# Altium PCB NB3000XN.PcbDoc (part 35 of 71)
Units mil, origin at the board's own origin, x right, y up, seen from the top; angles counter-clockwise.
Board outline 9527.56 x 6929.77 mil, 6 copper layers (Top Layer, GND+SHIELD, MidLayer1, MidLayer2, P2 - 3V3+5V0, Bottom Layer), stack 62.375 mil thick; 832 components, 1027 nets, 4655 pads, 4981 vias.
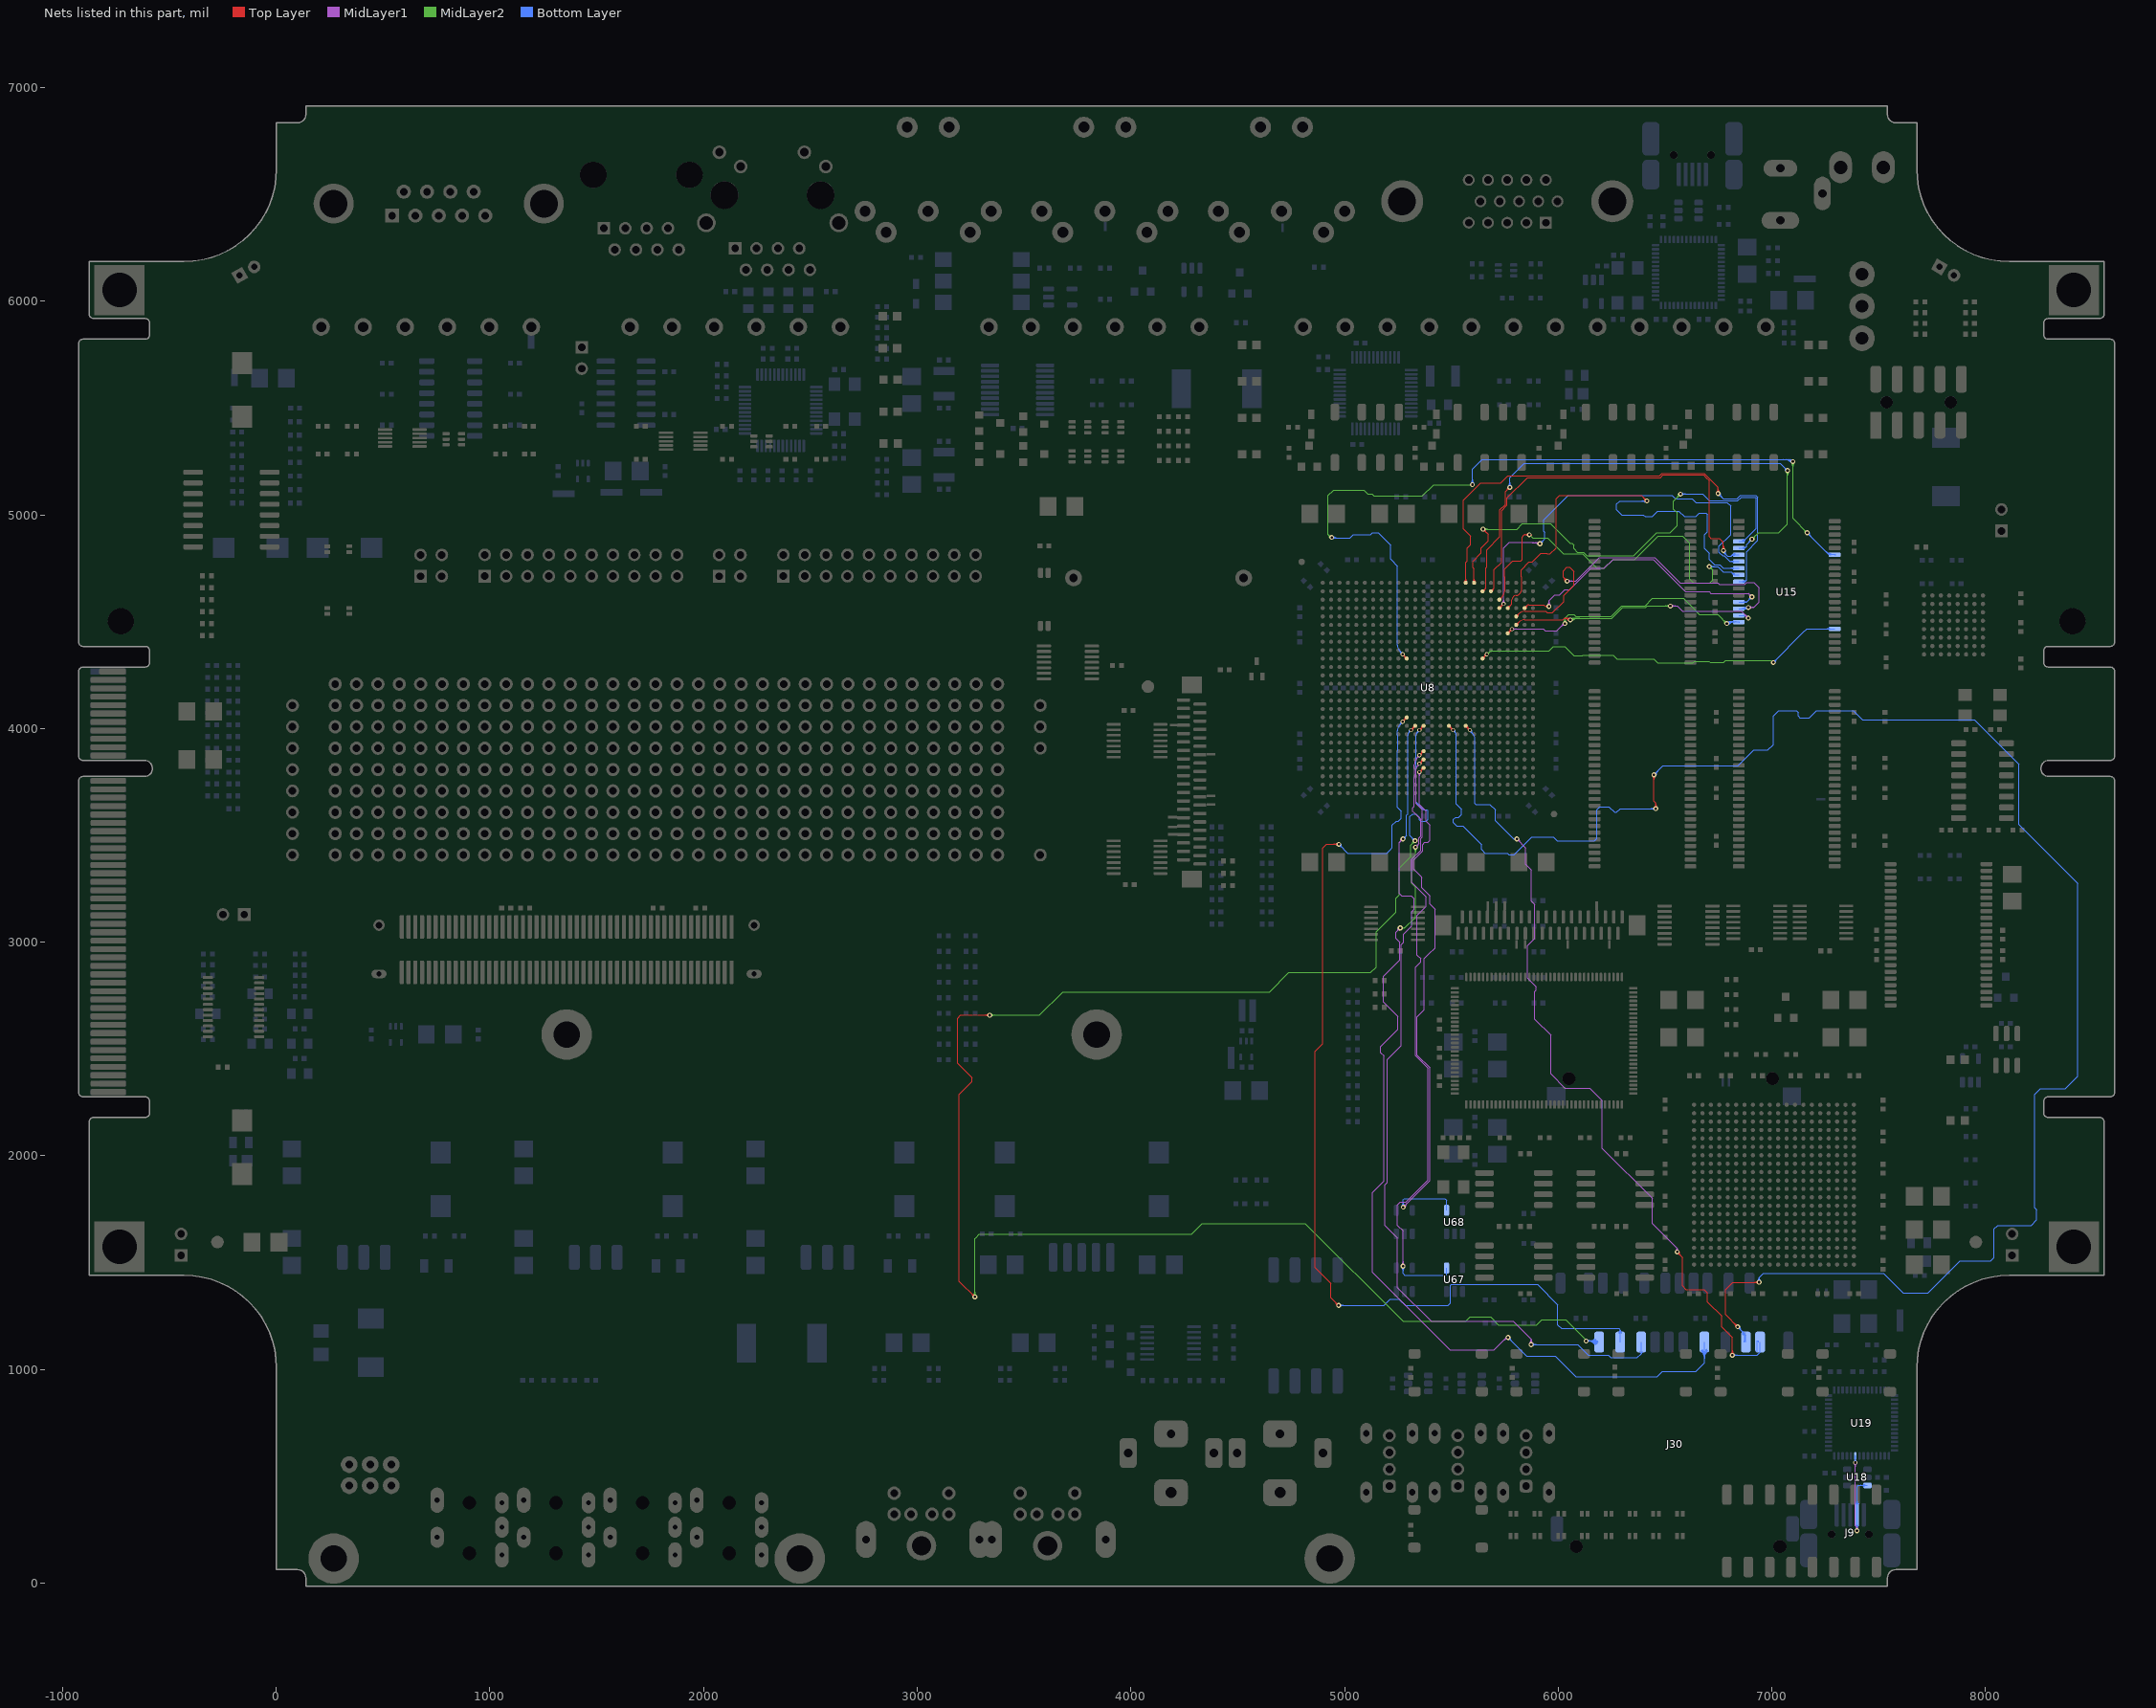
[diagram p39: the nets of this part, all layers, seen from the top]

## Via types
v1: diameter 23, hole 11.81, Top Layer to Bottom Layer, 3672 vias
v2: diameter 26, hole 11.81, Top Layer to Bottom Layer, 461 vias
v3: diameter 19, hole 11.81, Top Layer to Bottom Layer, tented both sides, 396 vias
v4: diameter 23.62, hole 11.81, Top Layer to Bottom Layer, 288 vias
v5: diameter 20, hole 11.81, Top Layer to Bottom Layer, 91 vias
v6: diameter 23, hole 11.81, Top Layer to Bottom Layer, tented both sides, 50 vias
v7: diameter 31, hole 11.81, Top Layer to Bottom Layer, 15 vias
v8: diameter 27.56, hole 11.81, Top Layer to Bottom Layer, tented both sides, 4 vias
v9: diameter 29, hole 11.81, Top Layer to Bottom Layer, 3 vias
v10: diameter 21, hole 11.81, Top Layer to Bottom Layer, 1 vias

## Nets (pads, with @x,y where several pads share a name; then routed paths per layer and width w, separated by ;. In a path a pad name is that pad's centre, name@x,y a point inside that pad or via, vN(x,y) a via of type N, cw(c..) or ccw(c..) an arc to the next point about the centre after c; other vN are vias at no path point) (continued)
DB_SRAM2.D8: U8.G23 U15.29 | length 1778.3
  Top Layer w4: U8.G23@5764.02,4445.91 v3(5783.7,4465.59) ; U8.G23@5764.02,4453.25 ccw(c5764.02,4470.97) 5776.55,4458.44 ccw(c5789.08,4445.91) U8.G23@5771.36,4445.91 ; U8.G23@5764.02,4453.41 ccw(c5764.02,4471.51) 5776.82,4458.71 ccw(c5789.62,4445.91) U8.G23@5771.52,4445.91 ; 5770.9,4452.79 cw(c5783.7,4439.98) 5783.7,4458.09 ccw(c5783.7,4439.98) 5770.9,4452.79 ; 5770.9,4452.79 ccw(c5758.09,4465.59) 5776.2,4465.59 cw(c5758.09,4465.59) 5770.9,4452.79
  MidLayer1 w4: v3(5783.7,4465.59) 5861.38,4465.59 5910,4465.59 5920,4465.59 5924.74,4465.59 5928.74,4465.59 5931.86,4465.59 5931.86,4465.37 5938.86,4458.37 5992.86,4458.37 6026.19,4491.71 v1(6031.86,4491.71) ; v3@5788.89,4460.4 cw(c5801.43,4447.86) 5801.43,4465.59 cw(c5801.43,4483.32) v3@5788.89,4470.78 ; 6005.97,4471.48 cw(c6031.86,4445.59) v1@6031.86,4482.21 ; 6012.79,4478.31 cw(c6031.86,4459.25) v1@6031.86,4486.21 ; 6019.62,4485.14 cw(c6031.86,4472.91) v1@6031.86,4490.21 ; 6019.65,4485.16 ccw(c6013.1,4491.71) v1@6022.36,4491.71 ; 5801.81,4465.59 cw(c5801.81,4483.7) 5789,4470.89 ccw(c5801.81,4483.7) 5801.81,4465.59 ; 5801.81,4465.59 ccw(c5801.81,4447.48) 5789,4460.29 cw(c5801.81,4447.48) 5801.81,4465.59
  MidLayer2 w4: v1@6025.14,4498.43 ccw(c6008.92,4514.64) 6031.86,4514.64 ccw(c6054.79,4514.64) v1@6038.57,4498.43 ; v1@6027.97,4495.6 ccw(c6018.58,4504.99) 6031.86,4504.99 ccw(c6045.14,4504.99) v1@6035.75,4495.6 ; v1(6031.86,4491.71) 6031.86,4516.71 6048.52,4533.37 6073.52,4533.37 6081.86,4525.04 6248.52,4525.04 6298.52,4575.04 6406.86,4575.04 6441.52,4609.71 6585.88,4609.71 6640.29,4555.29 ; 6640,4555 6661.29,4533.71 6747.19,4533.71 v1(6789.19,4491.71) ; v1@6779.69,4491.71 ccw(c6756.76,4491.71) 6772.97,4507.93 ccw(c6789.19,4524.14) v1@6789.19,4501.21 ; v1@6783.69,4491.71 ccw(c6770.41,4491.71) 6779.8,4501.1 ccw(c6789.19,4510.49) v1@6789.19,4497.21
  Bottom Layer w4: v1@6787.42,4493.48 cw(c6803.27,4477.63) 6803.27,4500.04 ; v1(6789.19,4491.71) 6797.52,4500.04 6845.59,4500.04 6848.52,4500.04 6848.52,4498.27 U15.29@6845.59,4498.27 ; v1@6790.25,4490.65 cw(c6812.93,4467.97) 6812.93,4500.04 ; v1@6793.08,4487.82 cw(c6822.59,4458.31) U15.29@6822.59,4500.04 ; v1@6795.91,4484.99 cw(c6832.24,4448.66) U15.29@6832.24,4500.04 ; 6804.43,4500.04 cw(c6804.43,4474.67) U15.29@6822.37,4492.61 ; 6813,4500.04 ccw(c6813,4513.3) U15.29@6822.37,4503.92 ; 6814.09,4500.04 cw(c6814.09,4484.33) U15.29@6825.2,4495.44
DB_SRAM2.D9: U8.F24 U15.30 | length 1657.7
  Top Layer w4: 6036.02,4516.71 cw(c6036.02,4499.6) v1@6051.79,4506.24 ; 6042.05,4516.71 cw(c6042.05,4502.14) v1@6055.47,4507.79 ; 6048.07,4516.71 cw(c6048.07,4504.68) v1@6059.16,4509.34 ; v1@6048.1,4504.69 ccw(c6030,4497.07) 6030,4516.71 ; v1(6056.86,4508.37) 6048.52,4516.71 6030,4516.71 ; 5815.92,4497.81 cw(c5843.27,4470.46) 5843.27,4509.14 ; 5815.92,4497.81 cw(c5843.27,4470.46) 5843.27,4509.14 ; 5815.92,4497.81 cw(c5803.39,4510.34) 5803.39,4492.62 ccw(c5803.39,4510.34) 5815.92,4497.81 ; 5815.92,4497.81 ccw(c5828.45,4485.28) 5810.73,4485.28 cw(c5828.45,4485.28) 5815.92,4497.81 ; 5843.27,4509.14 5910,4509.14 5920,4509.14 5924.74,4509.14 6022.43,4509.14 6030,4516.71
  MidLayer1 w4: v1(6525.19,4573.37) 6558.52,4573.37 6581.86,4550.04 6856.86,4550.04 v1(6890.19,4516.71) ; v1@6529.08,4569.49 cw(c6538.47,4560.1) 6538.47,4573.37 cw(c6538.47,4586.65) v1@6529.08,4577.26 ; v1@6531.91,4566.66 cw(c6548.13,4550.44) 6548.13,4573.37 cw(c6548.13,4596.31) v1@6531.91,4580.09 ; v1@6880.69,4516.71 ccw(c6857.76,4516.71) 6873.97,4532.93 ccw(c6890.19,4549.14) v1@6890.19,4526.21 ; v1@6884.69,4516.71 ccw(c6871.41,4516.71) 6880.8,4526.1 ccw(c6890.19,4535.49) v1@6890.19,4522.21
  MidLayer2 w4: v1@6055.09,4510.14 cw(c6070.94,4494.29) 6070.94,4516.71 ; v1(6056.86,4508.37) 6065.19,4516.71 6251.52,4516.71 6301.52,4566.71 6405,4566.71 6409.84,4566.71 6416.51,4573.37 v1(6525.19,4573.37) v1@6518.52,4566.71 ; v1@6057.92,4507.31 cw(c6080.6,4484.64) 6080.6,4516.71 ; v1@6060.75,4504.49 cw(c6090.25,4474.98) 6090.25,4516.71 ; v1@6063.57,4501.66 cw(c6099.91,4465.32) 6099.91,4516.71 ; v1@6518.47,4566.66 ccw(c6502.26,4550.44) 6502.26,4573.37 ccw(c6502.26,4596.31) v1@6518.47,4580.09 ; v1@6521.3,4569.49 ccw(c6511.91,4560.1) 6511.91,4573.37 ccw(c6511.91,4586.65) v1@6521.3,4577.26
  Bottom Layer w4: U15.30@6845.59,4529.76 6877.14,4529.76 ; U15.30@6870.05,4525.71 cw(c6877.14,4521.54) 6877.14,4529.76 ; U15.30@6870.05,4533.82 ccw(c6877.14,4537.99) 6877.14,4529.76 ; v1(6890.19,4516.71) 6877.14,4529.76
DB_SRAM2.D10: U8.E24 U15.31 | length 2064.2
  Top Layer w4: v1@6032.36,4690.04 ccw(c6009.42,4690.04) 6025.64,4706.26 ccw(c6041.86,4722.48) v1@6041.86,4699.54 ; v1@6036.36,4690.04 ccw(c6023.08,4690.04) 6032.47,4699.43 ccw(c6041.86,4708.82) v1@6041.86,4695.54 ; v1(6041.86,4690.04) 6023.52,4708.37 6023.52,4737.71 6040.82,4755 6053.23,4755 6073.52,4734.71 6073.52,4670.71 6026.19,4623.37 6026.19,4594.37 5973.52,4541.71 5947.98,4541.71 5941.18,4548.51 5924.74,4548.51 5920,4548.51 5910,4548.51 5843.27,4548.51 ; 5815.92,4537.18 cw(c5843.27,4509.83) 5843.27,4548.51 ; 5815.92,4537.18 cw(c5843.27,4509.83) 5843.27,4548.51 ; 5815.92,4537.18 cw(c5803.39,4549.71) 5803.39,4531.99 ccw(c5803.39,4549.71) 5815.92,4537.18 ; 5815.92,4537.18 ccw(c5828.45,4524.65) 5810.73,4524.65 cw(c5828.45,4524.65) 5815.92,4537.18
  MidLayer1 w4: v1(6041.86,4690.04) 6083.19,4690.04 6193.19,4800.04 6452.86,4800.04 6571.19,4681.71 6748.52,4681.71 6755.19,4675.04 6873.52,4675.04 6881.86,4683.37 6915.19,4683.37 6940.19,4658.37 6940.19,4591.71 6915.19,4566.71 v1(6890.19,4566.71) ; v1@6045.75,4686.15 cw(c6055.14,4676.76) 6055.14,4690.04 cw(c6055.14,4703.32) v1@6045.75,4693.93 ; v1@6048.57,4683.32 cw(c6064.79,4667.11) 6064.79,4690.04 cw(c6064.79,4712.98) v1@6048.57,4696.76 ; v1@6894.08,4562.82 cw(c6903.47,4553.43) 6903.47,4566.71 cw(c6903.47,4579.99) v1@6894.08,4570.6 ; v1@6896.91,4559.99 cw(c6913.13,4543.77) 6913.13,4566.71 cw(c6913.13,4589.64) v1@6896.91,4573.43
  Bottom Layer w4: U15.31@6845.59,4561.26 6884.74,4561.26 v1(6890.19,4566.71) ; U15.31@6854.1,4561.26 ccw(c6854.1,4602.8) v1@6883.47,4573.43 ; U15.31@6863.76,4561.26 ccw(c6863.76,4593.14) v1@6886.3,4570.6 ; U15.31@6868.81,4555.6 cw(c6882.46,4541.94) 6882.46,4561.26 cw(c6882.46,4580.57) U15.31@6868.81,4566.92 ; 6873.41,4561.26 ccw(c6873.41,4583.48) v1@6889.13,4567.77
DB_SRAM2.D11: U8.D25 U15.32 | length 1589
  Top Layer w4: v1@5948.52,4567.16 ccw(c5940.86,4562.98) 5940.86,4571.71 ; v1@5948.52,4576.26 cw(c5940.86,4580.43) 5940.86,4571.71 ; v1(5956.86,4571.71) 5940.86,4571.71 ; 5855.29,4576.55 cw(c5862.47,4569.37) 5862.47,4579.52 ; 5855.29,4576.55 cw(c5862.47,4569.37) 5862.47,4579.52 ; 5855.29,4576.55 ccw(c5867.83,4564.02) 5850.1,4564.02 cw(c5867.83,4564.02) 5855.29,4576.55 ; 5855.29,4576.55 cw(c5842.76,4589.08) 5842.76,4571.36 ccw(c5842.76,4589.08) 5855.29,4576.55 ; 5862.47,4579.52 5910,4579.52 5920,4579.52 5924.74,4579.52 5933.04,4579.52 5940.86,4571.71
  MidLayer1 w4: v1@5950.14,4578.43 ccw(c5933.92,4594.64) 5956.86,4594.64 ccw(c5979.79,4594.64) v1@5963.57,4578.43 ; v1@5952.97,4575.6 ccw(c5943.58,4584.99) 5956.86,4584.99 ccw(c5970.14,4584.99) v1@5960.75,4575.6 ; v1(5956.86,4571.71) 5956.86,4597.71 5984.19,4625.04 6006.86,4625.04 6031.86,4650.04 6054.52,4650.04 6154.52,4750.04 6215.19,4750.04 6256.86,4791.71 6445.19,4791.71 6595.19,4641.71 6706.86,4641.71 6715.19,4633.37 6890.19,4633.37 v1(6906.86,4616.71) ; v1@6897.36,4616.71 ccw(c6874.42,4616.71) 6890.64,4632.93 ccw(c6906.86,4649.14) v1@6906.86,4626.21 ; v1@6901.36,4616.71 ccw(c6888.08,4616.71) 6897.47,4626.1 ccw(c6906.86,4635.49) v1@6906.86,4622.21
  Bottom Layer w4: U15.32@6845.59,4592.75 6882.9,4592.75 v1(6906.86,4616.71) ; U15.32@6868.81,4587.1 cw(c6882.46,4573.44) 6882.46,4592.75 cw(c6882.46,4612.07) U15.32@6868.81,4598.41 ; v1@6897.36,4616.71 cw(c6874.42,4616.71) 6890.64,4600.49 cw(c6906.86,4584.27) v1@6906.86,4607.21 ; v1@6901.36,4616.71 cw(c6888.08,4616.71) 6897.47,4607.32 cw(c6906.86,4597.93) v1@6906.86,4611.21
DB_SRAM2.D12: U8.A18 U15.35 | length 2578.4
  Top Layer w4: U8.A18@5561.86,4687.43 ccw(c5549.06,4700.23) 5567.17,4700.23 ccw(c5585.27,4700.23) U8.A18@5572.47,4687.43 ; U8.A18@5561.97,4687.32 ccw(c5549.44,4699.85) 5567.17,4699.85 ccw(c5584.89,4699.85) U8.A18@5572.36,4687.32 ; U8.A18@5567.17,4682.13 5567.17,4710 5567.17,4720 5567.17,4724.74 5567.17,4777.64 5574.52,4785 5574.52,4845.71 5590.19,4861.37 5590.19,4900.04 5558.52,4931.71 5556.52,4933.71 5556.52,5068.35 5638.21,5150.04 5731.86,5150.04 5765.19,5183.37 6475.35,5183.37 6486.69,5194.71 6683.21,5194.71 6699.27,5178.64 6748.52,5129.39 v1(6748.52,5100.04) ; v1@6741.81,5106.76 ccw(c6725.59,5122.98) 6748.52,5122.98 ccw(c6771.46,5122.98) v1@6755.24,5106.76 ; v1@6744.64,5103.93 ccw(c6735.25,5113.32) 6748.52,5113.32 ccw(c6761.8,5113.32) v1@6752.41,5103.93
  Bottom Layer w4: v1@6748.52,5090.54 cw(c6748.52,5067.61) 6764.74,5083.82 cw(c6780.96,5100.04) v1@6758.02,5100.04 ; v1@6748.52,5094.54 cw(c6748.52,5081.26) 6757.91,5090.65 cw(c6767.3,5100.04) v1@6754.02,5100.04 ; v1(6748.52,5100.04) 6773.52,5075.04 6822.52,5075.04 6837.21,5075.04 6853.88,5091.71 6924.52,5091.71 6934.52,5081.71 6934.52,4880.71 6881.86,4828.04 6881.86,4695.24 ; U15.35@6845.59,4687.24 6873.86,4687.24 6881.86,4695.24 ; U15.35@6863.15,4687.24 ccw(c6868.38,4695) 6875,4688.38 ; U15.35@6865.39,4690.56 ccw(c6871.15,4699.09) 6878.43,4691.81 ; U15.35@6867.62,4693.87 ccw(c6873.91,4703.19) 6881.86,4695.24
DB_SRAM2.D13: U8.C22 U15.36 | length 2161.1
  Top Layer w4: 5804.97,4785.01 5801.16,4785.01 ; 5831.86,4855.37 5831.86,4790.71 5831.52,4790.37 ; v1@5858.47,4900.32 ccw(c5842.26,4884.11) 5842.26,4907.04 ccw(c5842.26,4929.98) v1@5858.47,4913.76 ; v1@5861.3,4903.15 ccw(c5851.91,4893.76) 5851.91,4907.04 ccw(c5851.91,4920.32) v1@5861.3,4910.93 ; v1@5873.52,4905.37 5871.86,4907.04 v1(5865.19,4907.04) 5841.84,4907.04 5831.52,4896.73 5831.52,4790.37 ; 5737.18,4615.92 ccw(c5709.83,4643.27) 5748.51,4643.27 ; 5737.18,4615.92 ccw(c5709.83,4643.27) 5748.51,4643.27 ; 5737.18,4615.92 ccw(c5749.71,4603.39) 5731.99,4603.39 cw(c5749.71,4603.39) 5737.18,4615.92 ; 5737.18,4615.92 cw(c5724.65,4628.45) 5724.65,4610.73 ccw(c5724.65,4628.45) 5737.18,4615.92 ; 5748.51,4643.27 5748.51,4710 5748.51,4720 5748.51,4724.74 5748.51,4732.36 5748.51,4746.44 5787.08,4785.01 5801.16,4785.01 ; 5801.19,4785.04 5826.19,4785.04 5831.52,4790.37
  MidLayer2 w4: 5873.52,4898.71 v1(5865.19,4907.04) 5880.86,4891.37 5951.15,4891.37 6025.49,4817.04 6065,4817.04 6115,4817.04 6182,4750.04 6215.04,4750.04 6256.71,4791.71 6359.19,4791.71 6467.52,4900.04 6581.86,4900.04 6615.19,4866.71 6615.19,4700.04 6633.52,4681.71 6710,4681.71 6723.52,4695.23 6723.52,4741.71 v1(6706.86,4758.37) ; v1@6706.86,4748.87 cw(c6706.86,4725.94) 6723.07,4742.16 cw(c6739.29,4758.37) v1@6716.36,4758.37 ; v1@6706.86,4752.87 cw(c6706.86,4739.6) 6716.25,4748.99 cw(c6725.64,4758.37) v1@6712.36,4758.37
  Bottom Layer w4: v1(6706.86,4758.37) 6747.19,4758.37 6773.52,4732.04 6810,4732.04 6823.3,4718.74 U15.36@6845.59,4718.74 ; v1@6710.75,4754.49 cw(c6720.14,4745.1) 6720.14,4758.37 cw(c6720.14,4771.65) v1@6710.75,4762.26 ; v1@6713.57,4751.66 cw(c6729.79,4735.44) 6729.79,4758.37 cw(c6729.79,4781.31) v1@6713.57,4765.09 ; 6812.37,4729.68 ccw(c6821.75,4739.06) U15.36@6825.67,4726.38 ; 6817.06,4724.99 ccw(c6823.96,4731.89) U15.36@6826.85,4722.56 ; 6817.72,4724.32 cw(c6812.14,4718.74) U15.36@6820.03,4718.74
DB_SRAM2.D14: U8.D23 U15.37 | length 2295.3
  Top Layer w4: v1@6405.69,5065.37 ccw(c6382.76,5065.37) 6398.97,5081.59 ccw(c6415.19,5097.81) v1@6415.19,5074.87 ; v1@6409.69,5065.37 ccw(c6396.41,5065.37) 6405.8,5074.76 ccw(c6415.19,5084.15) v1@6415.19,5070.87 ; v1(6415.19,5065.37) 6388.86,5091.71 6006.86,5091.71 5990.19,5075.04 5990.19,4845.44 5962.25,4817.5 5947.75,4817.5 5945.25,4820 5919.9,4820 5879.44,4779.54 5864.34,4779.54 5827.25,4742.45 5827.25,4720 5827.25,4710 5827.25,4643.27 cw(c5817.1,4643.27) 5824.28,4636.09 5824.27,4635.87 5816.36,4627.95 cw(c5803.39,4642.76) 5803.39,4623.07 ccw(c5803.39,4603.38) 5783.7,4603.39 5783.7,4591.94 cw(c5764.02,4591.94) 5777.94,4578.03 5777.94,4577.94 5776.55,4576.55 ; 5776.55,4576.55 ccw(c5789.08,4564.02) 5771.36,4564.02 cw(c5789.08,4564.02) 5776.55,4576.55 ; 5776.55,4576.55 cw(c5764.02,4589.08) 5764.02,4571.36 ccw(c5764.02,4589.08) 5776.55,4576.55
  Bottom Layer w4: v1@6408.47,5058.66 ccw(c6392.26,5042.44) 6392.26,5065.37 ccw(c6392.26,5088.31) v1@6408.47,5072.09 ; v1@6411.3,5061.49 ccw(c6401.91,5052.1) 6401.91,5065.37 ccw(c6401.91,5078.65) v1@6411.3,5069.26 ; v1(6415.19,5065.37) 6288.52,5065.37 6273.52,5050.37 6273.52,5025.04 6298.52,5000.04 6398.52,5000.04 6406.86,4991.71 6440.19,4991.71 6465.19,5016.71 6565.19,5016.71 6590.19,4991.71 6644.86,4991.71 6661.52,5008.37 6690.86,5008.37 6698.52,5000.71 6698.52,4920.71 6684.52,4906.71 6684.52,4843.37 6706.86,4821.04 6706.86,4791.71 6731.86,4766.71 6757.05,4766.71 6773.52,4750.23 U15.37@6845.59,4750.23 ; U15.37@6822.37,4744.58 ccw(c6808.72,4730.92) 6808.72,4750.23 ccw(c6808.72,4769.55) U15.37@6822.37,4755.89
DB_SRAM2.D15: U8.D22 U15.38 | length 2252.5
  Top Layer w4: U8.D22@5724.65,4564.02 v3(5744.33,4583.7) ; U8.D22@5724.65,4571.36 ccw(c5724.65,4589.08) 5737.18,4576.55 ccw(c5749.71,4564.02) U8.D22@5731.99,4564.02 ; U8.D22@5724.65,4571.52 ccw(c5724.65,4589.62) 5737.45,4576.82 ccw(c5750.25,4564.02) U8.D22@5732.15,4564.02 ; 5731.53,4570.9 cw(c5744.33,4558.09) 5744.33,4576.2 ccw(c5744.33,4558.09) 5731.53,4570.9 ; 5731.53,4570.9 ccw(c5718.72,4583.7) 5736.83,4583.7 cw(c5718.72,4583.7) 5731.53,4570.9
  MidLayer1 w4: v3@5739.14,4588.89 ccw(c5726.6,4601.43) 5744.33,4601.43 ccw(c5762.06,4601.43) v3@5749.52,4588.89 ; v3(5744.33,4583.7) 5744.33,4661.38 5744.33,4710 5744.33,4720 5744.33,4845.22 5771.82,4872.71 5877.33,4872.71 5880,4870.04 ; 5889.63,4870.04 cw(c5889.63,4839.74) v1@5911.1,4861.12 ; 5899.26,4870.04 cw(c5899.26,4849.32) v1@5913.94,4863.94 ; 5904.23,4870.04 ccw(c5904.23,4875.77) v1@5908.28,4871.72 ; v1@5908.27,4858.3 ccw(c5880,4830.15) 5880,4870.04 ; v1@5915,4867.56 5912.52,4870.04 5880,4870.04 ; 5744.33,4601.81 cw(c5726.22,4601.81) 5739.03,4589 ccw(c5726.22,4601.81) 5744.33,4601.81 ; 5744.33,4601.81 ccw(c5762.44,4601.81) 5749.63,4589 cw(c5762.44,4601.81) 5744.33,4601.81
  Bottom Layer w4: v1(5915,4865) 5937.5,4887.5 5937.5,4917.25 5931.86,4922.89 5931.86,4977.39 6046.17,5091.71 6531.86,5091.71 6548.52,5075.04 6627.17,5075.04 6643.84,5058.37 6790.86,5058.37 6807.52,5041.71 6807.52,4908.37 6752.86,4853.71 6752.86,4825.04 6769.52,4808.37 6777.21,4808.37 6803.86,4781.73 U15.38@6845.59,4781.73 ; v1@5915,4870.5 ccw(c5915,4883.78) 5924.39,4874.39 ccw(c5933.78,4865) v1@5920.5,4865 ; v1@5915,4874.5 ccw(c5915,4897.43) 5931.22,4881.22 ccw(c5947.43,4865) v1@5924.5,4865 ; U15.38@6822.37,4776.07 ccw(c6808.72,4762.42) 6808.72,4781.73 ccw(c6808.72,4801.04) U15.38@6822.37,4787.39
DB_SRAM2.NBHE: U8.B20 U15.40 | length 2900.4
  Top Layer w4: v1@5764.02,5129.04 cw(c5741.09,5129.04) 5757.31,5112.82 cw(c5773.52,5096.61) v1@5773.52,5119.54 ; v1@5768.02,5129.04 cw(c5754.75,5129.04) 5764.14,5119.65 cw(c5773.52,5110.26) v1@5773.52,5123.54 ; v1(5773.52,5129.04) 5753,5108.52 5753,5048.87 5727.52,5023.39 5727.52,4898.58 5665.19,4836.25 5665.19,4770 5665.19,4755.91 5661.41,4752.13 5661.41,4751.22 5661.41,4745 5661.41,4720 5661.41,4710 5661.41,4662.47 ; 5658.44,4655.29 ccw(c5651.26,4662.47) 5661.41,4662.47 ; 5658.44,4655.29 ccw(c5651.26,4662.47) 5661.41,4662.47 ; 5658.44,4655.29 cw(c5645.91,4667.83) 5645.91,4650.1 ccw(c5645.91,4667.83) 5658.44,4655.29 ; 5658.44,4655.29 ccw(c5670.97,4642.76) 5653.25,4642.76 cw(c5670.97,4642.76) 5658.44,4655.29
  MidLayer2 w4: v1(6906.86,4886.71) 6937.19,4917.04 7032.52,4917.04 ; v1@6906.86,4892.21 ccw(c6906.86,4905.49) 6916.25,4896.1 ccw(c6925.64,4886.71) v1@6912.36,4886.71 ; v1@6906.86,4896.21 ccw(c6906.86,4919.14) 6923.07,4902.93 ccw(c6939.29,4886.71) v1@6916.36,4886.71 ; v1@7066.81,5200.99 cw(c7050.59,5184.77) 7073.52,5184.77 cw(c7096.46,5184.77) v1@7080.24,5200.99 ; v1@7069.64,5203.82 cw(c7060.25,5194.43) 7073.52,5194.43 cw(c7086.8,5194.43) v1@7077.41,5203.82 ; v1(7073.52,5207.71) 7073.52,4958.04 7044.59,4929.11 ; 7032.52,4917.04 7044.59,4929.11 ; 7032.52,4917.04 7044.59,4929.11
  Bottom Layer w4: v1@5766.81,5135.76 ccw(c5750.59,5151.98) 5773.52,5151.98 ccw(c5796.46,5151.98) v1@5780.24,5135.76 ; v1@5769.64,5132.93 ccw(c5760.25,5142.32) 5773.52,5142.32 ccw(c5786.8,5142.32) v1@5777.41,5132.93 ; v1(5773.52,5129.04) 5773.52,5175.04 5840.19,5241.71 7039.52,5241.71 v1(7073.52,5207.71) ; U15.40@6845.59,4844.72 6873.15,4844.72 6881.15,4852.72 ; U15.40@6863.15,4844.72 ccw(c6868.03,4852.04) 6874.25,4845.82 ; U15.40@6865.37,4848.05 ccw(c6870.79,4856.18) 6877.7,4849.27 ; U15.40@6867.59,4851.38 ccw(c6873.55,4860.32) 6881.15,4852.72 ; v1@6897.36,4886.71 cw(c6874.42,4886.71) 6890.64,4870.49 cw(c6906.86,4854.27) v1@6906.86,4877.21 ; v1@6901.36,4886.71 cw(c6888.08,4886.71) 6897.47,4877.32 cw(c6906.86,4867.93) v1@6906.86,4881.21 ; v1(6906.86,4886.71) 6881.15,4861 6881.15,4852.72 ; v1@7064.02,5207.71 ccw(c7041.09,5207.71) 7057.31,5223.93 ccw(c7073.52,5240.14) v1@7073.52,5217.21 ; v1@7068.02,5207.71 ccw(c7054.75,5207.71) 7064.14,5217.1 ccw(c7073.52,5226.49) v1@7073.52,5213.21
DB_SRAM2.NBLE: U8.B21 U15.39 | length 2198.4
  Top Layer w4: v1@6766.81,4840.09 ccw(c6750.59,4856.31) 6773.52,4856.31 ccw(c6796.46,4856.31) v1@6780.24,4840.09 ; v1@6769.64,4837.26 ccw(c6760.25,4846.65) 6773.52,4846.65 ccw(c6786.8,4846.65) v1@6777.41,4837.26 ; v1(6773.52,4833.37) 6773.52,4871.37 6755.19,4889.71 6715.19,4889.71 6706.86,4898.04 6706.86,5159.75 6691.56,5175.04 6679.9,5186.71 6520.19,5186.71 6505,5186.71 6490,5186.71 6478.33,5175.04 5856.86,5175.04 5761,5079.18 5761,5045.56 5735.52,5020.08 5735.52,4778.71 5700.78,4743.97 5700.78,4724.74 5700.78,4720 5700.78,4710 5700.78,4662.47 ; 5697.81,4655.29 ccw(c5690.63,4662.47) 5700.78,4662.47 ; 5697.81,4655.29 ccw(c5690.63,4662.47) 5700.78,4662.47 ; 5697.81,4655.29 cw(c5685.28,4667.83) 5685.28,4650.1 ccw(c5685.28,4667.83) 5697.81,4655.29 ; 5697.81,4655.29 ccw(c5710.34,4642.76) 5692.62,4642.76 cw(c5710.34,4642.76) 5697.81,4655.29
  Bottom Layer w4: v1(6773.52,4833.37) 6773.52,4825.04 6792.34,4806.23 6809.03,4806.23 6816.03,4813.23 ; v1@6774.97,4832.98 ccw(c6787.75,4829.53) 6778.39,4820.17 ; v1@6778.83,4831.94 ccw(c6795.45,4827.46) 6783.28,4815.28 ; v1@6782.7,4830.9 ccw(c6803.15,4825.38) 6788.17,4810.39 ; 6807.64,4804.84 cw(c6820.95,4791.53) U15.39@6826.79,4809.42 ; 6810.03,4807.23 cw(c6816.38,4800.88) U15.39@6822.54,4807.41 ; 6812.25,4809.45 cw(c6823.22,4798.48) 6828.03,4813.23 ccw(c6822.03,4806.87) 6815.86,4813.05 ; 6812.94,4810.14 cw(c6819.21,4803.88) U15.39@6825.29,4810.32 ; 6816.86,4814.06 cw(c6825.49,4805.43) U15.39@6829.27,4817.03 ; U15.39@6820.65,4810.15 ccw(c6816.03,4808.23) 6816.03,4813.23 ; U15.39@6820.65,4816.3 cw(c6816.03,4818.23) 6816.03,4813.23 ; U15.39@6845.59,4813.23 6816.03,4813.23
DB_SRAM2.NCS: U8.K11 U15.6 | length 4588.6
  Top Layer w4: v3(5271.89,4347.48) U8.K11@5291.57,4327.8 ; U8.K11@5284.07,4327.8 ccw(c5265.97,4327.8) 5278.77,4340.6 ccw(c5291.57,4353.4) U8.K11@5291.57,4335.3 ; U8.K11@5284.23,4327.8 ccw(c5266.51,4327.8) 5279.04,4340.33 ccw(c5291.57,4352.86) U8.K11@5291.57,4335.14 ; 5284.69,4334.68 cw(c5297.5,4347.48) 5279.39,4347.48 ccw(c5297.5,4347.48) 5284.69,4334.68 ; 5284.69,4334.68 ccw(c5271.89,4321.87) 5271.89,4339.98 cw(c5271.89,4321.87) 5284.69,4334.68
  MidLayer2 w4: 4925.08,4906.82 ccw(c4933.31,4915.06) v1@4936.99,4904.01 ; 4925.98,4905.92 cw(c4915.05,4895) v1@4930.5,4895 ; 4929.65,4902.25 ccw(c4935.6,4908.2) v1@4938.26,4900.22 ; v1(4940,4895) v1@4940,4891.9 ; v1@4940.19,4891.71 v1@4940,4891.9 ; v1(5598.52,5141.71) 5416.71,5141.71 5363,5088 5138.31,5088 5128.31,5098 5108.56,5098 5089.86,5116.71 4948.52,5116.71 4923.52,5091.71 4923.52,4908.37 4938.45,4893.45 v1@4940,4891.9 ; v1@7091.81,5243.32 cw(c7075.59,5227.11) 7098.52,5227.11 cw(c7121.46,5227.11) v1@7105.24,5243.32 ; v1@7094.64,5246.15 cw(c7085.25,5236.76) 7098.52,5236.76 cw(c7111.8,5236.76) v1@7102.41,5246.15 ; v1(7098.52,5250.04) 7098.52,4983.37 v1(7165.19,4916.71) ; v1@7155.69,4916.71 ccw(c7132.76,4916.71) 7148.97,4932.93 ccw(c7165.19,4949.14) v1@7165.19,4926.21 ; v1@7159.69,4916.71 ccw(c7146.41,4916.71) 7155.8,4926.1 ccw(c7165.19,4935.49) v1@7165.19,4922.21
  Bottom Layer w4: v1(4940,4895) 4940,4891.9 4940.19,4891.71 5024.88,4891.71 5041.54,4908.37 5121.86,4908.37 5130.19,4916.71 5156.86,4916.71 5215.19,4858.37 5215.19,4793.5 5248.03,4760.66 5248.03,4720 5248.03,4710 5248.03,4503.9 5248.03,4484.48 5248.03,4410.36 5248.03,4390.86 ccw(c5289.76,4390.86) 5260.25,4361.35 ; v1@4941.06,4896.06 ccw(c4951.57,4906.57) 4951.57,4891.71 ; v1@4943.89,4898.89 ccw(c4961.23,4916.23) 4961.23,4891.71 ; v1@4946.72,4888.28 cw(c4954.99,4880.01) 4954.99,4891.71 ; v1@4946.72,4901.72 ccw(c4970.88,4925.88) 4970.88,4891.71 ; v3@5264.42,4348.13 ccw(c5246.38,4349.71) 5260.25,4361.35 ; v3@5272.54,4354.95 cw(c5274.12,4372.99) 5260.25,4361.35 ; v1@5591.81,5148.43 ccw(c5575.59,5164.64) 5598.52,5164.64 ccw(c5621.46,5164.64) v1@5605.24,5148.43 ; v1@5594.64,5145.6 ccw(c5585.25,5154.99) 5598.52,5154.99 ccw(c5611.8,5154.99) v1@5602.41,5145.6 ; v1(5598.52,5141.71) 5598.52,5213.73 5643.17,5258.37 7090.19,5258.37 v1(7098.52,5250.04) ; 7055.47,5258.37 cw(c7055.47,5206.99) v1@7091.81,5243.32 ; 7065.13,5258.37 cw(c7065.13,5216.64) v1@7094.64,5246.15 ; 7074.78,5258.37 cw(c7074.78,5226.3) v1@7097.46,5248.98 ; 7084.44,5258.37 cw(c7084.44,5235.96) v1@7100.29,5251.81 ; v1@7165.19,4907.21 cw(c7165.19,4884.27) 7181.41,4900.49 cw(c7197.63,4916.71) v1@7174.69,4916.71 ; v1@7165.19,4911.21 cw(c7165.19,4897.93) 7174.58,4907.32 cw(c7183.97,4916.71) v1@7170.69,4916.71 ; v1(7165.19,4916.71) 7265.19,4816.71 ; 7249.23,4832.67 ccw(c7276.85,4860.29) U15.6@7276.85,4821.23 ; 7256.06,4825.84 ccw(c7276.85,4846.63) U15.6@7276.85,4817.23 ; 7262.89,4819.01 ccw(c7276.85,4832.97) U15.6@7276.85,4813.23 ; 7265.94,4816.71 ccw(c7265.94,4824.14) U15.6@7271.19,4818.88 ; U15.6@7268.85,4813.1 ccw(c7265.19,4813.05) 7265.19,4816.71 ; U15.6@7294.41,4813.23 7298.52,4813.23 7298.52,4816.71 7265.19,4816.71
DB_SRAM2.NOE: U8.A19 U15.41 | length 2467.2
  Top Layer w4: U8.A19@5601.23,4687.43 ccw(c5588.43,4700.23) 5606.54,4700.23 ccw(c5624.64,4700.23) U8.A19@5611.84,4687.43 ; U8.A19@5601.34,4687.32 ccw(c5588.81,4699.85) 5606.54,4699.85 ccw(c5624.26,4699.85) U8.A19@5611.73,4687.32 ; U8.A19@5606.54,4682.13 5606.54,4710 5606.54,4720 5606.54,4724.74 5606.54,4746.05 5600.19,4752.39 5600.19,4782.37 5640.19,4822.37 5640.19,4845.19 5672.86,4877.86 5672.86,4909.04 v1(5648.52,4933.37) ; v1@5648.52,4923.87 cw(c5648.52,4900.94) 5664.74,4917.16 cw(c5680.96,4933.37) v1@5658.02,4933.37 ; v1@5648.52,4927.87 cw(c5648.52,4914.6) 5657.91,4923.99 cw(c5667.3,4933.37) v1@5654.02,4933.37
  MidLayer2 w4: v1(5648.52,4933.37) 5807.11,4933.37 5832.94,4959.21 5963.71,4959.21 6056.21,4866.71 6065.52,4866.71 6073.52,4858.71 6073.52,4842.04 6090.52,4825.04 6118.31,4825.04 6134.98,4808.37 6353.23,4808.37 6461.56,4916.71 6523.52,4916.71 6556.86,4950.04 6556.86,5010.71 6540.19,5027.37 6540.19,5065.04 v1(6572.52,5097.37) ; v1@5652.41,4929.49 cw(c5661.8,4920.1) 5661.8,4933.37 cw(c5661.8,4946.65) v1@5652.41,4937.26 ; v1@5655.24,4926.66 cw(c5671.46,4910.44) 5671.46,4933.37 cw(c5671.46,4956.31) v1@5655.24,4940.09 ; v1@6563.02,5097.37 cw(c6540.09,5097.37) 6556.31,5081.16 cw(c6572.52,5064.94) v1@6572.52,5087.87 ; v1@6567.02,5097.37 cw(c6553.75,5097.37) 6563.14,5087.99 cw(c6572.52,5078.6) v1@6572.52,5091.87
  Bottom Layer w4: v1(6572.52,5097.37) 6676.19,5097.37 6706.86,5066.71 6840.19,5066.71 6856.86,5083.37 6921.54,5083.37 6926.52,5078.39 6926.52,4936.37 6873.52,4883.37 6873.52,4876.22 U15.41@6845.59,4876.22 ; v1@6576.41,5093.49 cw(c6585.8,5084.1) 6585.8,5097.37 cw(c6585.8,5110.65) v1@6576.41,5101.26 ; v1@6579.24,5090.66 cw(c6595.46,5074.44) 6595.46,5097.37 cw(c6595.46,5120.31) v1@6579.24,5104.09 ; U15.41@6863.15,4880.22 ccw(c6863.15,4897.65) 6875.47,4885.32 ; U15.41@6863.15,4884.22 ccw(c6863.15,4911.3) 6882.3,4892.15 ; U15.41@6871.15,4876.22 cw(c6882.69,4876.22) 6874.53,4884.38
DB_SRAM2.NWE: U8.K20 U15.17 | length 1992.2
  Top Layer w4: U8.K20@5645.91,4327.8 v3(5665.59,4347.48) ; U8.K20@5645.91,4335.14 ccw(c5645.91,4352.86) 5658.44,4340.33 ccw(c5670.97,4327.8) U8.K20@5653.25,4327.8 ; U8.K20@5645.91,4335.3 ccw(c5645.91,4353.4) 5658.71,4340.6 ccw(c5671.51,4327.8) U8.K20@5653.41,4327.8 ; 5652.79,4334.68 cw(c5665.59,4321.87) 5665.59,4339.98 ccw(c5665.59,4321.87) 5652.79,4334.68 ; 5652.79,4334.68 ccw(c5639.98,4347.48) 5658.09,4347.48 cw(c5639.98,4347.48) 5652.79,4334.68
  MidLayer2 w4: v3@5666.24,4354.95 ccw(c5667.82,4372.99) 5679.46,4359.12 ccw(c5691.1,4345.25) v3@5673.06,4346.83 ; 5679.17,4358.87 cw(c5689.1,4348.94) 5689.1,4362.99 5782.64,4362.99 5910,4362.99 5920,4362.99 5924.74,4362.99 5956.86,4362.99 5977.24,4383.37 6031.86,4383.37 6074.19,4341.04 6115.19,4341.04 6116.86,4342.71 6256.86,4342.71 6274.52,4325.04 6448.52,4325.04 6465.19,4308.37 6630.52,4308.37 6637.52,4315.37 6705.19,4315.37 6711.19,4309.37 6774.19,4309.37 6783.52,4318.71 6997.52,4318.71 v1(7006.86,4309.37)
  Bottom Layer w4: v1(7006.86,4309.37) 7147.52,4450.04 7164.25,4466.77 U15.17@7294.41,4466.77 ; v1@7006.86,4314.87 ccw(c7006.86,4328.15) 7016.25,4318.76 ccw(c7025.64,4309.37) v1@7012.36,4309.37 ; v1@7006.86,4318.87 ccw(c7006.86,4341.81) 7023.07,4325.59 ccw(c7039.29,4309.37) v1@7016.36,4309.37 ; U15.17@7271.19,4461.11 ccw(c7257.54,4447.46) 7257.54,4466.77 ccw(c7257.54,4486.08) U15.17@7271.19,4472.43
DBSD.CLK: J30.5 U8.AA13 | length 5282.7
  Top Layer w4: v3(5350.63,3875.04) U8.AA13@5370.31,3894.72 ; U8.AA13@5362.81,3894.72 cw(c5344.71,3894.72) 5357.51,3881.92 cw(c5370.31,3869.12) U8.AA13@5370.31,3887.22 ; U8.AA13@5362.97,3894.72 cw(c5345.25,3894.72) 5357.78,3882.19 cw(c5370.31,3869.66) U8.AA13@5370.31,3887.38 ; 5363.43,3887.84 ccw(c5376.24,3875.04) 5358.13,3875.04 cw(c5376.24,3875.04) 5363.43,3887.84 ; 5363.43,3887.84 cw(c5350.63,3900.65) 5350.63,3882.54 ccw(c5350.63,3900.65) 5363.43,3887.84
  MidLayer1 w4: 5242.34,2902.19 5181.86,2841.71 5181.86,2720.35 5249.81,2652.4 5249.81,2592.31 5169.19,2511.69 5169.19,2483.35 5184.4,2468.14 5184.4,1881.84 5131.86,1829.29 5131.86,1454.04 5494.19,1091.71 5700.78,1091.71 5759.11,1150.04 v1(5765.19,1150.04) ; 5242.38,2902.19 5257.81,2917.62 5257.81,3000.09 5247.5,3010.4 ; 5247.5,3010.4 5240.19,3017.71 5240.19,3046.04 v1(5260.86,3066.71) ; v1@5251.36,3066.71 cw(c5228.42,3066.71) 5244.64,3050.49 cw(c5260.86,3034.27) v1@5260.86,3057.21 ; v1@5255.36,3066.71 cw(c5242.08,3066.71) 5251.47,3057.32 cw(c5260.86,3047.93) v1@5260.86,3061.21 ; 5326.77,3798.23 5326.77,3812.16 ; v1(5331.86,3445.04) 5348.52,3461.71 5348.52,3488.41 5356.86,3496.74 5356.86,3575.04 5323.52,3608.37 5320,3611.9 5320,3630 5326.77,3636.77 5326.77,3660 5326.77,3670 5326.77,3775.13 5326.77,3812.16 ; v1@5331.86,3450.54 ccw(c5331.86,3463.82) 5341.25,3454.43 ccw(c5350.64,3445.04) v1@5337.36,3445.04 ; v1@5331.86,3454.54 ccw(c5331.86,3477.48) 5348.07,3461.26 ccw(c5364.29,3445.04) v1@5341.36,3445.04 ; v3@5343.16,3874.39 cw(c5325.12,3872.81) 5338.99,3861.17 ; v3@5351.28,3867.57 ccw(c5352.86,3849.53) 5338.99,3861.17 ; 5738.6,1129.53 cw(c5765.19,1102.93) v1@5765.19,1140.54 ; 5745.43,1136.35 cw(c5765.19,1116.59) v1@5765.19,1144.54 ; 5752.25,1143.18 cw(c5765.19,1130.25) v1@5765.19,1148.54 ; 5753.27,1144.2 ccw(c5747.43,1150.04) v1@5755.69,1150.04 ; 5326.77,3812.16 5326.77,3831.66 cw(c5368.5,3831.66) 5338.99,3861.17
  MidLayer2 w4: v1(5260.86,3066.71) 5281.86,3066.71 ; v1@5264.99,3063.08 cw(c5273.01,3056.02) 5273.01,3066.71 cw(c5273.01,3077.39) v1@5264.99,3070.34 ; v1@5267.99,3060.44 cw(c5281.86,3048.25) 5281.86,3066.71 ; v1@5267.99,3072.98 ccw(c5281.86,3085.17) 5281.86,3066.71 ; v1@5325.14,3438.32 cw(c5308.92,3422.11) 5331.86,3422.11 cw(c5354.79,3422.11) v1@5338.57,3438.32 ; v1@5327.97,3441.15 cw(c5318.58,3431.76) 5331.86,3431.76 cw(c5345.14,3431.76) v1@5335.75,3441.15 ; v1(5331.86,3445.04) 5331.86,3410.71 5314.19,3393.04 5314.19,3276.04 5331.86,3258.37 5331.86,3116.71 5281.86,3066.71
  Bottom Layer w4: v1@5765.19,1140.54 cw(c5765.19,1117.61) 5781.41,1133.82 cw(c5797.63,1150.04) v1@5774.69,1150.04 ; v1@5765.19,1144.54 cw(c5765.19,1131.26) 5774.58,1140.65 cw(c5783.97,1150.04) v1@5770.69,1150.04 ; v1(5765.19,1150.04) 5837.14,1078.1 5852.23,1063 5986.19,1063 6082.48,966.71 6463.86,966.71 6488.86,991.71 6644.19,991.71 6684.53,1032.04 J30.5@6684.53,1128.35 ; J30.5@6669.79,1087.24 cw(c6634.23,1051.67) 6684.53,1051.67 cw(c6734.82,1051.67) J30.5@6699.26,1087.24 ; J30.5@6672.62,1090.06 cw(c6643.88,1061.33) 6684.53,1061.33 cw(c6725.17,1061.33) J30.5@6696.43,1090.06 ; J30.5@6675.45,1092.89 cw(c6653.54,1070.98) 6684.53,1070.98 cw(c6715.51,1070.98) J30.5@6693.6,1092.89
DBSD.CMD: J30.2 U8.V12 | length 4520.7
  Top Layer w4: v3(5311.26,3993.15) U8.V12@5330.94,4012.83 ; U8.V12@5323.44,4012.83 cw(c5305.34,4012.83) 5318.14,4000.03 cw(c5330.94,3987.23) U8.V12@5330.94,4005.33 ; U8.V12@5323.6,4012.83 cw(c5305.88,4012.83) 5318.41,4000.3 cw(c5330.94,3987.77) U8.V12@5330.94,4005.49 ; 5324.06,4005.95 cw(c5311.26,4018.76) 5311.26,4000.65 ccw(c5311.26,4018.76) 5324.06,4005.95 ; 5324.06,4005.95 ccw(c5336.87,3993.15) 5318.76,3993.15 cw(c5336.87,3993.15) 5324.06,4005.95
  MidLayer1 w4: v1@5264.02,3483.37 cw(c5241.09,3483.37) 5257.31,3467.16 cw(c5273.52,3450.94) v1@5273.52,3473.87 ; v1@5268.02,3483.37 cw(c5254.75,3483.37) 5264.14,3473.99 cw(c5273.52,3464.6) v1@5273.52,3477.87 ; v1(5273.52,3483.37) 5255.86,3465.71 5255.86,3228.37 5267.52,3216.71 5311.84,3216.71 5325.19,3203.36 5325.19,3154.04 5315.19,3144.04 5315.19,3075.04 5277.5,3037.35 5277.5,3000 5265.81,2988.31 5265.81,2517.33 5265.19,2516.71 5242.77,2494.28 5200.4,2451.92 5200.4,1875.21 5190.19,1865 5190.19,1675.04 5248.52,1616.71 5248.52,1383.37 5406.86,1225.04 5790.19,1225.04 5873.52,1141.71 v1(5873.52,1116.71) ; v1@5866.81,1123.43 ccw(c5850.59,1139.64) 5873.52,1139.64 ccw(c5896.46,1139.64) v1@5880.24,1123.43 ; v1@5869.64,1120.6 ccw(c5860.25,1129.99) 5873.52,1129.99 ccw(c5886.8,1129.99) v1@5877.41,1120.6
  Bottom Layer w4: v1(5273.52,3483.37) 5290.19,3500.04 5290.19,3594.69 5295.75,3600.25 5295.75,3660 5295.75,3670 5295.75,3876.1 5295.75,3969.64 cw(c5309.8,3969.64) 5299.87,3979.57 ; v1@5273.52,3488.87 ccw(c5273.52,3502.15) 5282.91,3492.76 ccw(c5292.3,3483.37) v1@5279.02,3483.37 ; v1@5273.52,3492.87 ccw(c5273.52,3515.81) 5289.74,3499.59 ccw(c5305.96,3483.37) v1@5283.02,3483.37 ; v3@5303.79,3992.5 cw(c5285.75,3990.92) 5299.62,3979.28 cw(c5313.49,3967.64) v3@5311.91,3985.68 ; v1(5873.52,1116.71) 6091.19,1116.71 6141.19,1066.71 6235,1066.71 6246.71,1055 6370,1055 6388.86,1073.86 ; v1@5877.41,1112.82 cw(c5886.8,1103.43) 5886.8,1116.71 cw(c5886.8,1129.99) v1@5877.41,1120.6 ; v1@5880.24,1109.99 cw(c5896.46,1093.77) 5896.46,1116.71 cw(c5896.46,1139.64) v1@5880.24,1123.43 ; J30.2@6382.79,1082.04 cw(c6380.31,1073.86) 6388.86,1073.86 ; J30.2@6388.86,1128.35 6388.86,1073.86 ; J30.2@6394.92,1082.04 ccw(c6397.4,1073.86) 6388.86,1073.86
DBSD.DAT0: J30.7 U8.V16 | length 9054.7
  Top Layer w4: U8.V16@5488.43,4005.33 cw(c5488.43,3987.23) 5501.23,4000.03 cw(c5514.03,4012.83) U8.V16@5495.93,4012.83 ; U8.V16@5488.43,4005.49 cw(c5488.43,3987.77) 5500.96,4000.3 cw(c5513.49,4012.83) U8.V16@5495.77,4012.83 ; U8.V16@5488.43,4012.83 v3(5508.11,3993.15) ; v1@6441.81,3776.66 cw(c6425.59,3760.44) 6448.52,3760.44 cw(c6471.46,3760.44) v1@6455.24,3776.66 ; v1@6444.64,3779.49 cw(c6435.25,3770.1) 6448.52,3770.1 cw(c6461.8,3770.1) v1@6452.41,3779.49 ; v1(6448.52,3783.37) 6448.52,3660 6456.86,3651.67 v1(6456.86,3625.04) ; v1@6450.14,3631.76 ccw(c6433.92,3647.98) 6456.86,3647.98 ccw(c6479.79,3647.98) v1@6463.57,3631.76 ; v1@6452.97,3628.93 ccw(c6443.58,3638.32) 6456.86,3638.32 ccw(c6470.14,3638.32) v1@6460.75,3628.93 ; v1@6830.69,1200.04 ccw(c6807.76,1200.04) 6823.97,1216.26 ccw(c6840.19,1232.48) v1@6840.19,1209.54 ; v1@6834.69,1200.04 ccw(c6821.41,1200.04) 6830.8,1209.43 ccw(c6840.19,1218.82) v1@6840.19,1205.54 ; v1(6840.19,1200.04) 6783.52,1256.71 6783.52,1375.04 6816.86,1408.37 v1(6940.19,1408.37) ; v1@6933.47,1401.66 ccw(c6917.26,1385.44) 6917.26,1408.37 ccw(c6917.26,1431.31) v1@6933.47,1415.09 ; v1@6936.3,1404.49 ccw(c6926.91,1395.1) 6926.91,1408.37 ccw(c6926.91,1421.65) v1@6936.3,1412.26 ; 5495.31,4005.95 cw(c5482.5,3993.15) 5500.61,3993.15 ccw(c5482.5,3993.15) 5495.31,4005.95 ; 5495.31,4005.95 ccw(c5508.11,4018.76) 5508.11,4000.65 cw(c5508.11,4018.76) 5495.31,4005.95
  Bottom Layer w4: v3@5507.46,3985.68 cw(c5505.88,3967.64) 5519.75,3979.28 cw(c5533.62,3990.92) v3@5515.58,3992.5 ; 5519.5,3979.57 cw(c5509.57,3969.64) 5523.62,3969.64 5523.62,3876.1 5523.62,3670 5523.62,3660 5523.62,3646.37 5546.99,3623 5546.99,3598.01 5533.98,3585 5520,3585 5510,3575 5510,3560 5525,3545 5553.69,3545 5553.69,3544.9 5641.9,3456.69 5641.9,3433.1 5657.92,3417.08 5762.44,3417.08 5769.98,3409.55 5794.34,3409.55 5876.67,3491.87 5976.66,3491.87 5994.48,3474.04 6170.21,3474.04 6182.19,3486.02 6182.19,3620.56 6195,3633.37 6238.19,3633.37 6263.19,3608.37 6273.52,3608.37 6290.19,3625.04 v1(6456.86,3625.04) ; v1(6448.52,3783.37) 6490.19,3825.04 6773.52,3825.04 6774.52,3826.04 6841.19,3826.04 6915.19,3900.04 6981.86,3900.04 7006.86,3925.04 7006.86,4058.37 7031.86,4083.37 7115.19,4083.37 7123.52,4075.04 7123.52,4058.37 7131.86,4050.04 7176.5,4050.04 7209.84,4083.37 7381.86,4083.37 7423.52,4041.71 7948.52,4041.71 8156.86,3833.37 8156.86,3550.04 8431.86,3275.04 8431.86,2371.86 8373.94,2313.94 8257.07,2313.94 8230,2286.87 8230,1757.18 8240.19,1746.99 8240.19,1700.04 8215.19,1675.04 8056.86,1675.04 8040.19,1658.37 8040.19,1525.04 8023.52,1508.37 7881.86,1508.37 7731.86,1358.37 7615.19,1358.37 7523.52,1450.04 6959.86,1450.04 6940.19,1430.37 ; v1@6448.52,3788.87 ccw(c6448.52,3802.15) 6457.91,3792.76 ccw(c6467.3,3783.37) v1@6454.02,3783.37 ; v1@6448.52,3792.87 ccw(c6448.52,3815.81) 6464.74,3799.59 ccw(c6480.96,3783.37) v1@6458.02,3783.37 ; v1@6450.14,3618.32 ccw(c6433.92,3602.11) 6433.92,3625.04 ccw(c6433.92,3647.98) v1@6450.14,3631.76 ; v1@6452.97,3621.15 ccw(c6443.58,3611.76) 6443.58,3625.04 ccw(c6443.58,3638.32) v1@6452.97,3628.93 ; v1@6840.19,1190.54 cw(c6840.19,1167.61) 6856.41,1183.82 cw(c6872.63,1200.04) v1@6849.69,1200.04 ; v1@6840.19,1194.54 cw(c6840.19,1181.26) 6849.58,1190.65 cw(c6858.97,1200.04) v1@6845.69,1200.04 ; v1(6840.19,1200.04) 6860.08,1180.16 6860.19,1180.04 6878.23,1162.01 J30.7@6878.23,1128.35 ; 6860.45,1179.78 cw(c6849.82,1169.16) J30.7@6863.22,1162.35 ; 6863.01,1177.22 ccw(c6876.76,1190.97) J30.7@6877.54,1171.55 ; J30.7@6864.35,1175.89 cw(c6854.99,1166.53) J30.7@6866.78,1160.54 ; J30.7@6871.23,1128.35 6871.23,1133.37 6873.52,1133.37 J30.7@6873.52,1166.71 ; v1@6933.68,1415.29 ccw(c6919.47,1430.37) 6940.19,1430.37 ; v1@6936.42,1412.38 ccw(c6928.19,1421.11) 6940.19,1421.11 ccw(c6952.19,1421.11) v1@6943.96,1412.38 ; v1(6940.19,1408.37) 6940.19,1430.37 ; v1@6946.7,1415.29 cw(c6960.91,1430.37) 6940.19,1430.37
DBSD.DAT1: J30.8 U8.V18 | length 4275.8
  Top Layer w4: U8.V18@5567.17,4005.33 cw(c5567.17,3987.23) 5579.97,4000.03 cw(c5592.77,4012.83) U8.V18@5574.67,4012.83 ; U8.V18@5567.17,4005.49 cw(c5567.17,3987.77) 5579.7,4000.3 cw(c5592.23,4012.83) U8.V18@5574.51,4012.83 ; U8.V18@5567.17,4012.83 v3(5586.85,3993.15) ; v1@6556.86,1540.54 cw(c6556.86,1517.61) 6573.07,1533.82 cw(c6589.29,1550.04) v1@6566.36,1550.04 ; v1@6556.86,1544.54 cw(c6556.86,1531.26) 6566.25,1540.65 cw(c6575.64,1550.04) v1@6562.36,1550.04 ; v1(6556.86,1550.04) 6581.86,1525.04 6581.86,1391.71 6598.52,1375.04 6681.86,1375.04 6698.52,1358.37 6698.52,1316.71 6765.19,1250.04 6765.19,1200.04 6815.19,1150.04 v1(6815.19,1066.71) ; v1@6808.47,1073.43 ccw(c6792.26,1089.64) 6815.19,1089.64 ccw(c6838.13,1089.64) v1@6821.91,1073.43 ; v1@6811.3,1070.6 ccw(c6801.91,1079.99) 6815.19,1079.99 ccw(c6828.47,1079.99) v1@6819.08,1070.6 ; 5574.05,4005.95 cw(c5561.24,3993.15) 5579.35,3993.15 ccw(c5561.24,3993.15) 5574.05,4005.95 ; 5574.05,4005.95 ccw(c5586.85,4018.76) 5586.85,4000.65 cw(c5586.85,4018.76) 5574.05,4005.95
  MidLayer1 w4: v1@5806.86,3473.87 cw(c5806.86,3450.94) 5823.07,3467.16 cw(c5839.29,3483.37) v1@5816.36,3483.37 ; v1@5806.86,3477.87 cw(c5806.86,3464.6) 5816.25,3473.99 cw(c5825.64,3483.37) v1@5812.36,3483.37 ; v1(5806.86,3483.37) 5848.52,3441.71 5848.52,3363.85 5874.52,3337.85 5874.52,3191.71 5890.19,3176.04 5890.19,3016.71 5856.86,2983.37 5856.86,2831.46 5897.69,2790.62 5897.69,2776.13 5890.36,2768.79 5890.36,2677.83 5890.19,2677.66 5890.19,2639.34 5965.19,2564.34 5965.19,2383.37 6031.86,2316.71 6148.52,2316.71 6206.86,2258.37 6206.86,2035.37 6440.19,1802.04 6440.19,1683.37 6556.86,1566.71 ; v1@6552.02,1558.22 ccw(c6546.99,1566.71) 6556.86,1566.71 ; v1(6556.86,1550.04) 6556.86,1566.71 ; v1@6561.7,1558.22 cw(c6566.73,1566.71) 6556.86,1566.71
  Bottom Layer w4: v3@5585.55,3985.76 cw(c5582.4,3967.93) 5597.24,3978.32 ; v3@5594.24,3991.85 ccw(c5612.07,3988.7) 5597.24,3978.32 ; v1(5806.86,3483.37) 5791.19,3483.37 5705.52,3569.04 5705.52,3620 5680.15,3645.37 5614.63,3645.37 5610.62,3649.38 5610.62,3660 5610.62,3670 5610.62,3953.78 ccw(c5586.85,3953.78) 5603.66,3970.59 5597.24,3978.32 ; v1(6815.19,1066.71) 6931.71,1066.71 6945.16,1080.16 J30.8@6945.16,1128.35 ; v1@6819.08,1062.82 cw(c6828.47,1053.43) 6828.47,1066.71 cw(c6828.47,1079.99) v1@6819.08,1070.6 ; v1@6821.91,1059.99 cw(c6838.13,1043.77) 6838.13,1066.71 cw(c6838.13,1089.64) v1@6821.91,1073.43 ; J30.8@6931.86,1083.37 6931.86,1128.35 6931.86,1133.37 6938.16,1133.37 J30.8@6938.16,1128.35
DBSD.DAT2: J30.9 U8.V13 | length 9173
  Top Layer w4: v1@3260.5,1340 ccw(c3237.56,1340) 3253.78,1356.22 ccw(c3270,1372.43) v1@3270,1349.5 ; v1@3264.5,1340 ccw(c3251.22,1340) 3260.61,1349.39 ccw(c3270,1358.78) v1@3270,1345.5 ; v1(3270,1340) 3197.19,1412.81 3197.19,2287.81 3256.86,2347.48 3256.86,2365 3189.19,2432.67 3189.19,2644.19 3203.37,2658.37 v1(3339.52,2658.37) ; v1@3332.81,2651.66 ccw(c3316.59,2635.44) 3316.59,2658.37 ccw(c3316.59,2681.31) v1@3332.81,2665.09 ; v1@3335.64,2654.49 ccw(c3326.25,2645.1) 3326.25,2658.37 ccw(c3326.25,2671.65) v1@3335.64,2662.26 ; v3(5350.63,3993.15) U8.V13@5370.31,4012.83 ; U8.V13@5362.81,4012.83 cw(c5344.71,4012.83) 5357.51,4000.03 cw(c5370.31,3987.23) U8.V13@5370.31,4005.33 ; U8.V13@5362.97,4012.83 cw(c5345.25,4012.83) 5357.78,4000.3 cw(c5370.31,3987.77) U8.V13@5370.31,4005.49 ; 5363.43,4005.95 cw(c5350.63,4018.76) 5350.63,4000.65 ccw(c5350.63,4018.76) 5363.43,4005.95 ; 5363.43,4005.95 ccw(c5376.24,3993.15) 5358.13,3993.15 cw(c5376.24,3993.15) 5363.43,4005.95
  MidLayer2 w4: v1@3263.28,1346.72 ccw(c3247.06,1362.93) 3270,1362.93 ccw(c3292.93,1362.93) v1@3276.72,1346.72 ; v1@3266.11,1343.89 ccw(c3256.72,1353.28) 3270,1353.28 ccw(c3283.28,1353.28) v1@3273.89,1343.89 ; v1(3270,1340) 3270,1613.18 3273.52,1616.71 3290.19,1633.37 4284,1633.37 4334,1683.37 4815.19,1683.37 5273.52,1225.04 5567.16,1225.04 5587.4,1245.29 5683.63,1245.29 5720.71,1208.21 5898.01,1208.21 5923,1233.21 6035.73,1233.21 6051.73,1217.21 6130.86,1138.08 v1(6130.86,1133.37) ; v1(3339.52,2658.37) 3573.37,2658.37 3681.71,2766.71 3730,2766.71 4648.52,2766.71 4740.19,2858.37 5122.52,2858.37 5148.52,2884.37 5148.52,3050.04 5240.19,3141.71 5240.19,3205.08 5255.86,3220.75 5255.86,3346.71 5309.19,3400.04 5309.19,3453.71 v1(5330.52,3475.04) ; v1@3343.41,2654.49 cw(c3352.8,2645.1) 3352.8,2658.37 cw(c3352.8,2671.65) v1@3343.41,2662.26 ; v1@3346.24,2651.66 cw(c3362.46,2635.44) 3362.46,2658.37 cw(c3362.46,2681.31) v1@3346.24,2665.09 ; v1@5321.02,3475.04 cw(c5298.09,3475.04) 5314.31,3458.82 cw(c5330.52,3442.61) v1@5330.52,3465.54 ; v1@5325.02,3475.04 cw(c5311.75,3475.04) 5321.13,3465.65 cw(c5330.52,3456.26) v1@5330.52,3469.54
  Bottom Layer w4: v1@5321.02,3475.04 ccw(c5298.09,3475.04) 5314.31,3491.26 ccw(c5330.52,3507.48) v1@5330.52,3484.54 ; v1@5325.02,3475.04 ccw(c5311.75,3475.04) 5321.14,3484.43 ccw(c5330.52,3493.82) v1@5330.52,3480.54 ; v1(5330.52,3475.04) 5306.52,3499.04 5306.52,3588.39 5318.17,3600.04 5334.52,3600.04 5351.19,3583.37 5351.19,3573.37 5357.86,3566.71 5381.86,3566.71 5390.19,3575.04 5390.19,3616.71 5386.9,3620 5370,3620 5335.12,3654.88 5335.12,3660 5335.12,3670 5335.12,3876.1 5335.12,3969.64 cw(c5349.17,3969.64) 5339.24,3979.57 ; v3@5343.16,3992.5 cw(c5325.12,3990.92) 5338.99,3979.28 cw(c5352.86,3967.64) v3@5351.28,3985.68 ; v1@6134.75,1129.49 cw(c6144.14,1120.1) 6144.14,1133.37 cw(c6144.14,1146.65) v1@6134.75,1137.26 ; v1@6137.57,1126.66 cw(c6153.79,1110.44) 6153.79,1133.37 cw(c6153.79,1156.31) v1@6137.57,1140.09 ; v1@6140.32,1133.37 cw(c6140.32,1078.18) J30.9@6179.93,1116.62 ; 6146.85,1133.37 ccw(c6146.85,1166.51) J30.9@6170.27,1143.08 ; 6147.61,1133.37 cw(c6147.61,1098.13) J30.9@6175.02,1120.28 ; 6149.77,1133.37 cw(c6149.77,1087.36) J30.9@6182.8,1119.41 ; 6153.85,1133.37 ccw(c6153.85,1166.51) J30.9@6177.27,1143.08 ; 6155.98,1133.37 cw(c6155.98,1104.9) J30.9@6178.13,1122.79 ; 6156.5,1133.37 ccw(c6156.5,1156.85) J30.9@6173.1,1140.25 ; 6159.23,1133.37 cw(c6159.23,1096.53) J30.9@6185.67,1122.19 ; 6163.5,1133.37 ccw(c6163.5,1156.85) J30.9@6180.1,1140.25 ; 6168.69,1133.37 cw(c6168.69,1105.71) J30.9@6188.54,1124.98 ; J30.9@6177.06,1113.84 ccw(c6130.86,1069) v1(6130.86,1133.37) 6185.01,1133.37 J30.9@6185.01,1128.35
DBSD.DAT3: J30.1 U8.U11 | length 5249.3
  Top Layer w4: v1@4963.02,1300.04 ccw(c4940.09,1300.04) 4956.31,1316.26 ccw(c4972.52,1332.48) v1@4972.52,1309.54 ; v1@4966.81,3451.66 ccw(c4950.59,3435.44) 4950.59,3458.37 ccw(c4950.59,3481.31) v1@4966.81,3465.09 ; v1@4967.02,1300.04 ccw(c4953.75,1300.04) 4963.14,1309.43 ccw(c4972.52,1318.82) v1@4972.52,1305.54 ; v1@4969.64,3454.49 ccw(c4960.25,3445.1) 4960.25,3458.37 ccw(c4960.25,3471.65) v1@4969.64,3462.26 ; v1(4972.52,1300.04) 4936.58,1335.99 4936.58,1402.3 4862,1476.88 4862,2488.52 4865.19,2491.71 4898.52,2525.04 4898.52,3441.71 4915.19,3458.37 v1(4973.52,3458.37) ; v3(5271.89,4032.52) U8.U11@5291.57,4052.2 ; U8.U11@5284.07,4052.2 cw(c5265.97,4052.2) 5278.77,4039.4 cw(c5291.57,4026.6) U8.U11@5291.57,4044.7 ; U8.U11@5284.23,4052.2 cw(c5266.51,4052.2) 5279.04,4039.67 cw(c5291.57,4027.14) U8.U11@5291.57,4044.86 ; 5284.69,4045.32 cw(c5271.89,4058.13) 5271.89,4040.02 ccw(c5271.89,4058.13) 5284.69,4045.32 ; 5284.69,4045.32 ccw(c5297.5,4032.52) 5279.39,4032.52 cw(c5297.5,4032.52) 5284.69,4045.32
  Bottom Layer w4: v1(4972.52,1300.04) 5185,1300.04 5214.96,1330 5255,1330 5285.29,1299.71 5484.71,1299.71 5496.86,1311.86 5496.86,1395 5500.23,1398.37 5902.56,1398.37 5998.52,1302.41 5998.52,1208.37 6015.19,1191.71 6283.29,1191.71 6290.43,1184.57 ; v1@4973.52,3448.87 cw(c4973.52,3425.94) 4989.74,3442.16 cw(c5005.96,3458.37) v1@4983.02,3458.37 ; v1@4973.52,3452.87 cw(c4973.52,3439.6) 4982.91,3448.99 cw(c4992.3,3458.37) v1@4979.02,3458.37 ; v1(4973.52,3458.37) 5015.19,3416.71 5197.52,3416.71 5215.19,3434.37 5223.86,3443.04 5223.86,3547.58 5242.98,3566.71 5252.52,3566.71 5265.19,3579.37 5265.19,3613.18 5248.03,3630.34 5248.03,3660 5248.03,3670 5248.03,3876.1 5248.03,3895.52 5248.03,3969.64 5248.03,3989.14 cw(c5289.76,3989.14) 5260.25,4018.65 ; v1@4976.41,1296.15 cw(c4985.8,1286.76) 4985.8,1300.04 cw(c4985.8,1313.32) v1@4976.41,1303.93 ; v1@4979.24,1293.32 cw(c4995.46,1277.11) 4995.46,1300.04 cw(c4995.46,1322.98) v1@4979.24,1306.76 ; v3@5264.42,4031.87 cw(c5246.38,4030.29) 5260.25,4018.65 ; v3@5272.54,4025.05 ccw(c5274.12,4007.01) 5260.25,4018.65 ; J30.1@6283.25,1174.28 ccw(c6279.47,1184.57) 6290.43,1184.57 ; J30.1@6284.63,1170.53 ccw(c6281.58,1178.84) 6290.43,1178.84 ccw(c6299.28,1178.84) J30.1@6296.23,1170.53 ; J30.1@6290.43,1128.35 6290.43,1184.57 ; J30.1@6297.61,1174.28 cw(c6301.39,1184.57) 6290.43,1184.57
DBSD.DETECT: U8.AC13 U68.4 | length 2936.6
  Top Layer w4: v3(5350.63,3796.3) U8.AC13@5370.31,3815.98 ; U8.AC13@5362.81,3815.98 cw(c5344.71,3815.98) 5357.51,3803.18 cw(c5370.31,3790.38) U8.AC13@5370.31,3808.48 ; U8.AC13@5362.97,3815.98 cw(c5345.25,3815.98) 5357.78,3803.45 cw(c5370.31,3790.92) U8.AC13@5370.31,3808.64 ; 5363.43,3809.1 ccw(c5376.24,3796.3) 5358.13,3796.3 cw(c5376.24,3796.3) 5363.43,3809.1 ; 5363.43,3809.1 cw(c5350.63,3821.91) 5350.63,3803.8 ccw(c5350.63,3821.91) 5363.43,3809.1
  MidLayer1 w4: v1(5274.86,1759.71) 5399.19,1884.04 5399.19,2413.02 5339.86,2472.35 5339.86,2651.33 5373.52,2685 5373.52,2923.19 5395.5,2945.16 5395.5,2945.5 5423.52,2973.53 5423.52,3154.04 5399.19,3178.37 5399.19,3218 5362.5,3254.69 5362.5,3302.73 5356.96,3308.27 5323.52,3341.71 5323.52,3385.71 5365.19,3427.37 5365.19,3457.04 5374.86,3466.71 5390,3466.71 5399.7,3476.41 5399.7,3548.86 5381.86,3566.71 5381.86,3614.35 5350.63,3645.58 5350.63,3660 5350.63,3670 5350.63,3718.62 v3(5350.63,3796.3) ; v3@5345.44,3791.11 cw(c5332.9,3778.57) 5350.63,3778.57 cw(c5368.36,3778.57) v3@5355.82,3791.11 ; 5284.25,1769.1 cw(c5274.86,1778.49) 5274.86,1765.21 ccw(c5274.86,1778.49) 5284.25,1769.1 ; 5284.25,1769.1 ccw(c5293.64,1759.71) 5280.36,1759.71 cw(c5293.64,1759.71) 5284.25,1769.1 ; 5291.07,1775.93 cw(c5274.86,1792.14) 5274.86,1769.21 ccw(c5274.86,1792.14) 5291.07,1775.93 ; 5291.07,1775.93 ccw(c5307.29,1759.71) 5284.36,1759.71 cw(c5307.29,1759.71) 5291.07,1775.93 ; 5350.63,3778.19 cw(c5368.74,3778.19) 5355.93,3791 ccw(c5368.74,3778.19) 5350.63,3778.19 ; 5350.63,3778.19 ccw(c5332.52,3778.19) 5345.33,3791 cw(c5332.52,3778.19) 5350.63,3778.19
  Bottom Layer w4: v1@5268.14,1766.43 ccw(c5251.92,1782.64) 5274.86,1782.64 ccw(c5297.79,1782.64) v1@5281.57,1766.43 ; v1@5270.97,1763.6 ccw(c5261.58,1772.99) 5274.86,1772.99 ccw(c5288.14,1772.99) v1@5278.75,1763.6 ; v1(5274.86,1759.71) 5274.86,1794.86 5280.37,1800.37 5469.63,1800.37 5477.6,1792.4 U68.4@5477.6,1745.12
DBSD.PROTECT: U8.AB13 U67.4 | length 3170.7
  Top Layer w4: v3(5350.63,3835.67) U8.AB13@5370.31,3855.35 ; U8.AB13@5362.81,3855.35 cw(c5344.71,3855.35) 5357.51,3842.55 cw(c5370.31,3829.75) U8.AB13@5370.31,3847.85 ; U8.AB13@5362.97,3855.35 cw(c5345.25,3855.35) 5357.78,3842.82 cw(c5370.31,3830.29) U8.AB13@5370.31,3848.01 ; 5363.43,3848.47 cw(c5350.63,3861.28) 5350.63,3843.17 ccw(c5350.63,3861.28) 5363.43,3848.47 ; 5363.43,3848.47 ccw(c5376.24,3835.67) 5358.13,3835.67 cw(c5376.24,3835.67) 5363.43,3848.47
  MidLayer1 w4: v1(5273.52,1483.37) 5273.52,1650.04 5248.52,1675.04 5248.52,1770 5261.9,1783.37 5287.21,1783.37 5391.19,1887.35 5391.19,2409.71 5385.52,2415.37 5331.86,2469.04 5331.86,2883.37 5356.86,2908.37 5356.86,2923.19 5340.19,2939.85 5340.19,3124.04 5382.86,3166.71 5382.86,3211.71 5315.19,3279.37 5315.19,3388.69 5356.86,3430.36 5356.86,3485.42 5364.86,3493.42 5364.86,3620.04 5335,3649.9 5335,3660 5335,3670 5335,3685 ; 5335.12,3685 5335.12,3812.16 ; 5335.12,3798.23 5335.12,3812.16 ; 5339.24,3822.09 ccw(c5349.17,3812.16) 5335.12,3812.16 ; v3@5343.16,3835.02 cw(c5325.12,3833.44) 5338.99,3821.8 cw(c5352.86,3810.16) v3@5351.28,3828.2 ; 5273.52,1496.65 ccw(c5286.8,1496.65) 5277.41,1487.26 cw(c5286.8,1496.65) 5273.52,1496.65 ; 5273.52,1496.65 cw(c5260.25,1496.65) 5269.64,1487.26 ccw(c5260.25,1496.65) 5273.52,1496.65 ; 5273.52,1506.31 ccw(c5296.46,1506.31) 5280.24,1490.09 cw(c5296.46,1506.31) 5273.52,1506.31 ; 5273.52,1506.31 cw(c5250.59,1506.31) 5266.81,1490.09 ccw(c5250.59,1506.31) 5273.52,1506.31
  Bottom Layer w4: v1@5266.81,1476.66 cw(c5250.59,1460.44) 5273.52,1460.44 cw(c5296.46,1460.44) v1@5280.24,1476.66 ; v1@5269.64,1479.49 cw(c5260.25,1470.1) 5273.52,1470.1 cw(c5286.8,1470.1) v1@5277.41,1479.49 ; v1(5273.52,1483.37) 5273.52,1450 5282.15,1441.37 5473,1441.37 5477.6,1445.97 U67.4@5477.6,1475.12
DBUSB#.DMINUS: J9.2 U18.6 U19.9 | length 842.9
  MidLayer1 w5: v5@7385.17,559.04 cw(c7372.37,546.23) 7390.47,546.23 cw(c7408.58,546.23) v5@7395.78,559.04 ; v5(7390.47,564.34) 7390.47,269.53 7398.5,261.5 ; v4@7393.69,252.97 ccw(c7388.55,261.5) 7398.5,261.5 ; v4@7397.01,243.5 v4(7398.5,245) 7398.5,261.5 ; v4@7403.31,252.97 cw(c7408.46,261.5) 7398.5,261.5
  Bottom Layer w5: v4@7391.92,251.58 ccw(c7376.02,267.48) 7398.5,267.48 ccw(c7420.98,267.48) v4@7405.09,251.58 ; J9.2@7393.31,269.53 cw(c7380.78,257) 7398.5,257 cw(c7416.23,257) J9.2@7403.7,269.53 ; J9.2@7393.31,370.47 ccw(c7380.78,383) 7398.5,383 ccw(c7416.23,383) J9.2@7403.7,370.47 ; v4(7398.5,245) J9.2@7398.5,320 7398.5,451.1 7405,457.6 U18.6@7447.24,457.6 ; U18.6@7433.36,449.62 ccw(c7414.11,430.37) 7414.11,457.6 ccw(c7414.11,484.83) U18.6@7433.36,465.57 ; U18.6@7436.9,453.16 ccw(c7426.18,442.44) 7426.18,457.6 ccw(c7426.18,472.76) U18.6@7436.9,462.04
  Bottom Layer w8: v5@7386.23,568.58 ccw(c7375.99,578.82) 7390.47,578.82 ccw(c7404.96,578.82) v5@7394.72,568.58 ; v5(7390.47,564.34) U19.9@7390.47,595.67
